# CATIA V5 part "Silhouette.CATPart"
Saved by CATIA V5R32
Part number: Part1
Bounding box of the stored display mesh (mm): x -117 to 50, y -75 to 75, z 0 to 147
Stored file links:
  D:\PROJECTS\Project 2022\CATIA V5 6R 2022\Resources\Part Files\c17_catia_v6_6r2022_prt\Silhouette.CATPart
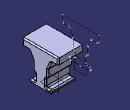
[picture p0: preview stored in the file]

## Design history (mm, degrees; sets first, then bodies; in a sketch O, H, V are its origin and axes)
Set1
  Sketch1 on yz-plane, origin (0, 0, 0), H (0, 1, 0), V (0, 0, 1)
    line L1 (0, 0) -> (45, 0)
    line L2 (45, 0) -> (45, 15)
    line L3 (45, 15) -> (22, 15)
    point P1 (45, 0)
    point P2 (45, 15)
    reference intersected line E1 through (0, 0) direction (0, 1) from zx-plane
    point P5 (0, 0)
    construction line L4 through (0, 0) direction (-1, 0)
    construction line L5 through (0, 0) direction (0, 1)
    point P6 (-45, 0)
    point P7 (-45, 15)
    line L6 (0, 0) -> (-45, 0)
    line L7 (-45, 0) -> (-45, 15)
    line L8 (-45, 15) -> (-22, 15)
    point P8 (-75, 147)
    line L9 (-75, 147) -> (75, 147)
    point P9 (75, 147)
    line L10 (75, 147) -> (75, 117)
    point P10 (75, 117)
    line L11 (75, 117) -> (45, 117)
    point P11 (45, 117)
    line L12 (45, 117) -> (30, 85)
    point P12 (30, 85)
    line L13 (30, 85) -> (30, 50)
    point P13 (30, 50)
    line L14 (30, 50) -> (22, 50)
    point P14 (22, 50)
    line L15 (22, 50) -> (22, 15)
    point P15 (22, 15)
    point P16 (-45, 15)
    point P17 (-75, 147)
    point P18 (-75, 117)
    point P19 (-45, 117)
    point P20 (-30, 85)
    point P21 (-30, 50)
    point P22 (-22, 50)
    point P23 (-22, 15)
    line L16 (-75, 147) -> (-75, 117)
    line L17 (-75, 117) -> (-45, 117)
    line L18 (-45, 117) -> (-30, 85)
    line L19 (-30, 85) -> (-30, 50)
    line L20 (-30, 50) -> (-22, 50)
    line L21 (-22, 50) -> (-22, 15)
    length L2 = 15
    length L10 = 30
    length L9 = 150
    length L11 = 30
    length L13 = 35
    length L15 = 35
    length L14 = 8
    distance P11 P12 V = 32
    distance P12 P11 H = 15
    horizontal: L1 H, L3 H, L9 H, L11 H, L14 H
    vertical: L2 V, L10 V, L13 V, L15 V
    symmetry: O P5 E1, H L4 E1, V L5 E1, P1 P6 E1, P2 P7 E1, L1 L6 E1, L2 L7 E1, L3 L8 E1, P2 P16 L5, P9 P17 L5, P10 P18 L5, P11 P19 L5, P12 P20 L5, P13 P21 L5, P14 P22 L5, P15 P23 L5, L10 L16 L5, L11 L17 L5, L12 L18 L5, L13 L19 L5, L14 L20 L5, L15 L21 L5, P9 P8 L5
    coincidence: P11 L2, O P5, P8 P17
Body1 (main body)
  Pad1: profile Sketch1, direction (1, 0, 0), length 50, mirrored extent
  Fillet1: radius 5, on edge [face of Pad1 from Sketch1.L10 | end face of Pad1]; edge [face of Pad1 from Sketch1.L16 | end face of Pad1]; edge [face of Pad1 from Sketch1.L17 | end face of Pad1]; edge [face of Pad1 from Sketch1.L18 | end face of Pad1]; edge [face of Pad1 from Sketch1.L19 | end face of Pad1]; edge [face of Pad1 from Sketch1.L20 | end face of Pad1]; edge [face of Pad1 from Sketch1.L21 | end face of Pad1]; edge [face of Pad1 from Sketch1.L8 | end face of Pad1]; edge [face of Pad1 from Sketch1.L3 | end face of Pad1]; edge [face of Pad1 from Sketch1.L15 | end face of Pad1]; edge [face of Pad1 from Sketch1.L14 | end face of Pad1]; end face of Pad1; edge [face of Pad1 from Sketch1.L10 | face of Pad1 from Sketch1.L11]; edge [face of Pad1 from Sketch1.L17 | face of Pad1 from Sketch1.L16]; edge [face of Pad1 from Sketch1.L11 | face of Pad1 from Sketch1.L12]; edge [face of Pad1 from Sketch1.L12 | face of Pad1 from Sketch1.L13]; edge [face of Pad1 from Sketch1.L13 | face of Pad1 from Sketch1.L14]; edge [face of Pad1 from Sketch1.L14 | face of Pad1 from Sketch1.L15]; edge [face of Pad1 from Sketch1.L15 | face of Pad1 from Sketch1.L3]; edge [face of Pad1 from Sketch1.L18 | face of Pad1 from Sketch1.L17]; edge [face of Pad1 from Sketch1.L19 | face of Pad1 from Sketch1.L18]; edge [face of Pad1 from Sketch1.L20 | face of Pad1 from Sketch1.L19]; edge [face of Pad1 from Sketch1.L21 | face of Pad1 from Sketch1.L20]; edge [face of Pad1 from Sketch1.L8 | face of Pad1 from Sketch1.L21]; face of Pad1 from Sketch1.L3; edge [face of Pad1 from Sketch1.L7 | face of Pad1 from Sketch1.L8]; edge [face of Pad1 from Sketch1.L2 | face of Pad1 from Sketch1.L1]; edge [face of Pad1 from Sketch1.L6 | face of Pad1 from Sketch1.L7]
  Plane1: type Offset, RefPlane start face of Pad1, Offset 67, reversed
  Silhouette1: Direction yz-plane, ShadowPlane Plane1, Support Fillet1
